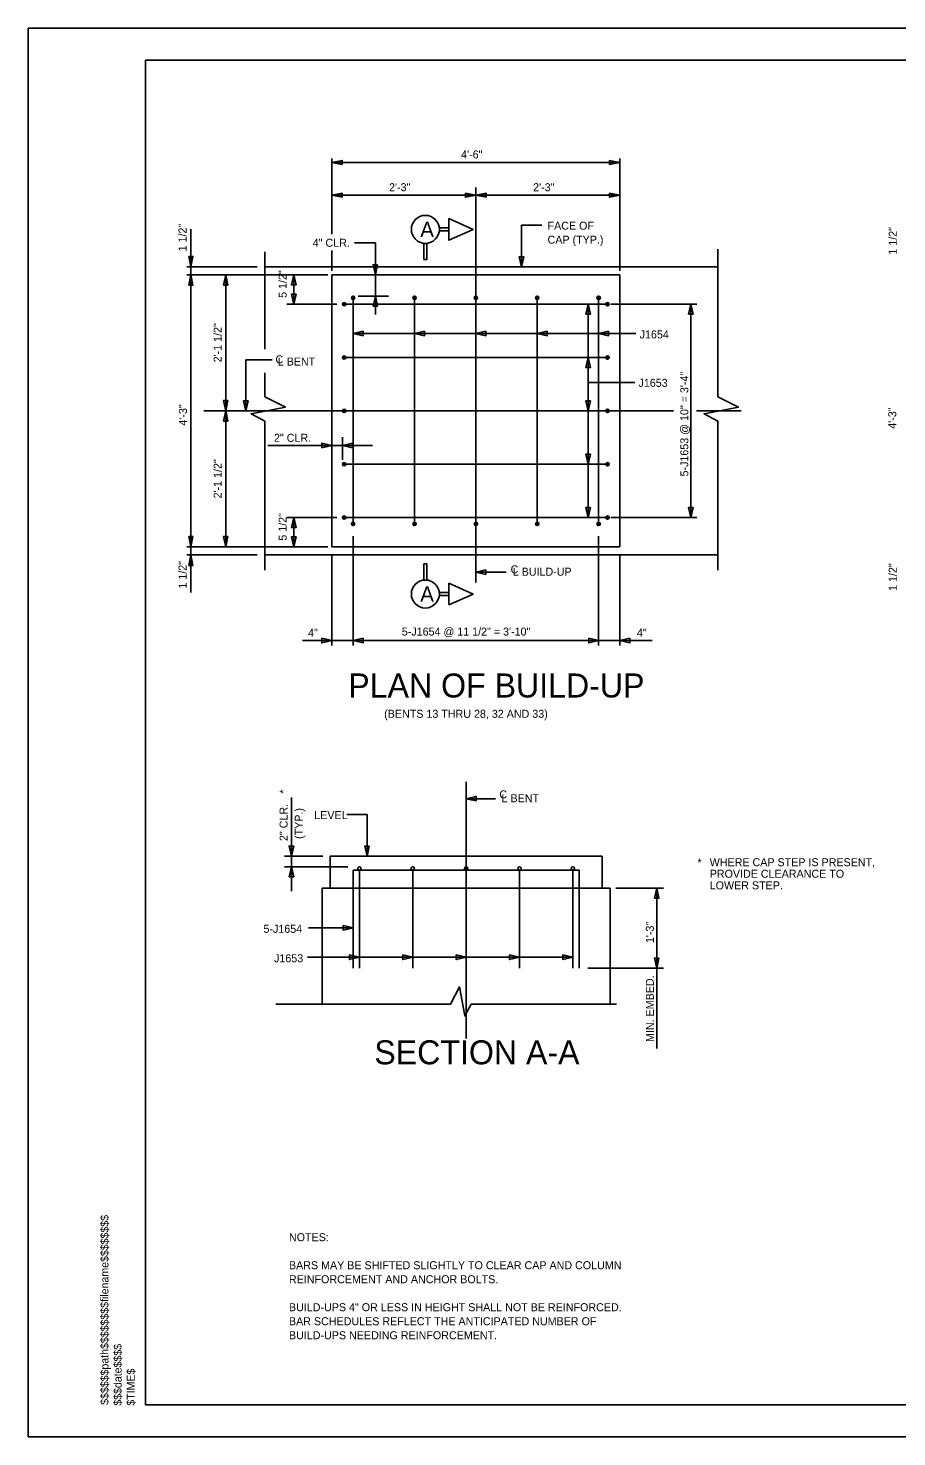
# Model space of a CAD drawing. Extents: x -133.1 to -97, y -58.4 to -36.4.
# Drawn here: x -133.14 to -119.58, y -58.4 to -36.4 of the extents above; entities that cross this region are included whole.
import ezdxf

# ---------------------------------------------------------------- set-up
doc = ezdxf.new("R2010")
doc.units = 0
for name, color, linetype in [('BR_AUTO DIMENSION', 7, 'Continuous'), ('BR_BORDER LINES', 7, 'Continuous'), ('BR_CENTER LINES', 7, 'Continuous'), ('BR_CONCRETE', 7, 'Continuous'), ('BR_REBAR', 7, 'Continuous'), ('BR_TEXT', 7, 'Continuous'), ('Default', 7, 'Continuous'), ('Level 31', 7, 'Continuous'), ('RD_SHT_ID', 7, 'Continuous')]:
    doc.layers.add(name, color=color, linetype=linetype)

msp = doc.modelspace()

# ---------------------------------------------------------------- linework, layer by layer
at = {"layer": 'BR_AUTO DIMENSION'}
for p, q in [((-128.4, -39.615), (-128.4, -38.433)), ((-128.4, -38.495), (-123.9, -38.495)), ((-123.9, -40.188), (-123.9, -38.433)), ((-126.15, -38.889), (-126.15, -39.254)), ((-128.4, -39.008), (-126.15, -39.008)), ((-123.9, -39.008), (-126.15, -39.008)), ((-130.599, -40.25), (-130.599, -39.536)), ((-125.436, -39.475), (-125.436, -40.125)), ((-125.436, -39.475), (-125.119, -39.475)), ((-127.72, -39.75), (-128.044, -39.75)), ((-127.72, -40.871), (-127.72, -39.75)), ((-128.4, -40.188), (-128.4, -39.869)), ((-129.565, -40.125), (-130.666, -40.125)), ((-128.463, -40.25), (-130.662, -40.25)), ((-130.599, -44.5), (-130.599, -40.25)), ((-130.057, -40.25), (-130.057, -42.375)), ((-128.995, -40.25), (-128.995, -40.709)), ((-127.988, -40.584), (-127.513, -40.584)), ((-128.321, -40.709), (-129.102, -40.709)), ((-124.396, -40.709), (-124.396, -44.042)), ((-124.045, -40.709), (-122.702, -40.709)), ((-122.795, -44.042), (-122.795, -40.709)), ((-128.067, -41.166), (-123.652, -41.166)), ((-129.743, -41.576), (-129.743, -42.375)), ((-129.331, -41.576), (-129.743, -41.576)), ((-124.396, -41.935), (-123.667, -41.935)), ((-130.114, -42.375), (-129.978, -42.375)), ((-130.057, -42.375), (-130.057, -44.5)), ((-128.233, -42.784), (-128.233, -43.139)), ((-127.765, -42.916), (-129.399, -42.916)), ((-128.321, -44.042), (-129.102, -44.042)), ((-128.995, -44.5), (-128.995, -44.042)), ((-124.045, -44.042), (-122.702, -44.042)), ((-128.067, -44.333), (-128.067, -46.038)), ((-124.233, -44.333), (-124.233, -46.038)), ((-129.565, -44.625), (-130.666, -44.625)), ((-128.463, -44.5), (-130.662, -44.5)), ((-130.599, -44.5), (-130.599, -45.214)), ((-128.4, -44.625), (-128.4, -46.038)), ((-123.9, -44.625), (-123.9, -46.038)), ((-126.15, -44.895), (-125.679, -44.895)), ((-128.856, -45.963), (-123.398, -45.963)), ((-129.03, -48.412), (-129.03, -49.877)), ((-126.302, -48.432), (-125.842, -48.432)), ((-128.167, -48.679), (-127.85, -48.679)), ((-127.85, -48.679), (-127.85, -49.329)), ((-128.541, -49.329), (-129.139, -49.329)), ((-128.152, -49.496), (-129.139, -49.496)), ((-123.964, -49.83), (-123.22, -49.83)), ((-123.327, -49.83), (-123.327, -52.333)), ((-128.067, -50.449), (-128.762, -50.449)), ((-124.635, -50.908), (-128.78, -50.908)), ((-128.385, -50.908), (-128.465, -50.908)), ((-127.135, -50.908), (-127.215, -50.908)), ((-126.302, -50.908), (-126.382, -50.908)), ((-125.968, -50.908), (-126.048, -50.908)), ((-125.468, -50.908), (-125.548, -50.908)), ((-124.635, -50.908), (-124.715, -50.908)), ((-124.401, -51.08), (-123.22, -51.08)), ((-123.964, -51.08), (-123.22, -51.08))]:
    msp.add_line(p, q, dxfattribs=at)
for points in [[(-128.238, -38.527), (-128.4, -38.495), (-128.238, -38.464)], [(-124.063, -38.464), (-123.9, -38.495), (-124.063, -38.527)], [(-128.238, -39.039), (-128.4, -39.008), (-128.238, -38.976)], [(-126.313, -38.976), (-126.15, -39.008), (-126.313, -39.039)], [(-125.988, -39.039), (-126.15, -39.008), (-125.988, -38.976)], [(-124.063, -38.976), (-123.9, -39.008), (-124.063, -39.039)], [(-130.631, -39.963), (-130.599, -40.125), (-130.568, -39.963)], [(-125.4, -39.969), (-125.436, -40.125), (-125.472, -39.969)], [(-130.631, -40.413), (-130.599, -40.25), (-130.568, -40.413)], [(-130.089, -40.413), (-130.057, -40.25), (-130.026, -40.413)], [(-128.959, -40.406), (-128.995, -40.25), (-129.031, -40.406)], [(-127.684, -40.094), (-127.72, -40.25), (-127.756, -40.094)], [(-129.031, -40.553), (-128.995, -40.709), (-128.959, -40.553)], [(-127.756, -40.74), (-127.72, -40.584), (-127.684, -40.74)], [(-124.432, -40.865), (-124.396, -40.709), (-124.36, -40.865)], [(-122.831, -40.865), (-122.795, -40.709), (-122.759, -40.865)], [(-127.911, -41.13), (-128.067, -41.166), (-127.911, -41.202)], [(-126.952, -41.13), (-127.108, -41.166), (-126.952, -41.202)], [(-125.994, -41.13), (-126.15, -41.166), (-125.994, -41.202)], [(-125.036, -41.13), (-125.192, -41.166), (-125.036, -41.202)], [(-124.077, -41.13), (-124.233, -41.166), (-124.077, -41.202)], [(-124.432, -41.698), (-124.396, -41.542), (-124.36, -41.698)], [(-130.026, -42.213), (-130.057, -42.375), (-130.089, -42.213)], [(-129.707, -42.219), (-129.743, -42.375), (-129.779, -42.219)], [(-124.36, -42.219), (-124.396, -42.375), (-124.432, -42.219)], [(-130.089, -42.538), (-130.057, -42.375), (-130.026, -42.538)], [(-128.556, -42.952), (-128.4, -42.916), (-128.556, -42.88)], [(-128.077, -42.88), (-128.233, -42.916), (-128.077, -42.952)], [(-124.36, -43.053), (-124.396, -43.209), (-124.432, -43.053)], [(-124.36, -43.886), (-124.396, -44.042), (-124.432, -43.886)], [(-122.759, -43.886), (-122.795, -44.042), (-122.831, -43.886)], [(-129.031, -44.198), (-128.995, -44.042), (-128.959, -44.198)], [(-130.568, -44.338), (-130.599, -44.5), (-130.631, -44.338)], [(-130.026, -44.338), (-130.057, -44.5), (-130.089, -44.338)], [(-128.959, -44.344), (-128.995, -44.5), (-129.031, -44.344)], [(-130.631, -44.788), (-130.599, -44.625), (-130.568, -44.788)], [(-125.994, -44.931), (-126.15, -44.895), (-125.994, -44.859)], [(-128.556, -45.927), (-128.4, -45.963), (-128.556, -45.999)], [(-127.911, -45.999), (-128.067, -45.963), (-127.911, -45.927)], [(-124.389, -45.927), (-124.233, -45.963), (-124.389, -45.999)], [(-123.744, -45.927), (-123.9, -45.963), (-123.744, -45.999)], [(-126.146, -48.468), (-126.302, -48.432), (-126.146, -48.396)], [(-128.994, -49.173), (-129.03, -49.329), (-129.066, -49.173)], [(-127.814, -49.173), (-127.85, -49.329), (-127.886, -49.173)], [(-129.066, -49.652), (-129.03, -49.496), (-128.994, -49.652)], [(-123.363, -49.986), (-123.327, -49.83), (-123.291, -49.986)], [(-128.223, -50.413), (-128.067, -50.449), (-128.223, -50.485)], [(-128.124, -50.872), (-127.968, -50.908), (-128.124, -50.944)], [(-127.291, -50.872), (-127.135, -50.908), (-127.291, -50.944)], [(-126.458, -50.872), (-126.302, -50.908), (-126.458, -50.944)], [(-125.624, -50.872), (-125.468, -50.908), (-125.624, -50.944)], [(-124.791, -50.872), (-124.635, -50.908), (-124.791, -50.944)], [(-123.291, -50.924), (-123.327, -51.08), (-123.363, -50.924)]]:
    msp.add_lwpolyline(points, close=True, dxfattribs=at)
at = {"layer": 'BR_BORDER LINES'}
for p, q in [((-97.642, -36.899), (-131.308, -36.899)), ((-131.308, -57.899), (-131.308, -36.899)), ((-131.308, -57.899), (-97.642, -57.899))]:
    msp.add_line(p, q, dxfattribs=at)
at = {"layer": 'BR_CENTER LINES'}
for p, q in [((-126.15, -39.008), (-126.15, -45.056)), ((-130.399, -42.375), (-123.065, -42.375)), ((-122.703, -42.375), (-122.007, -42.375)), ((-126.302, -48.171), (-126.302, -52.18))]:
    msp.add_line(p, q, dxfattribs=at)
at = {"layer": 'BR_CONCRETE'}
for p, q in [((-129.444, -40.125), (-122.37, -40.125)), ((-128.4, -40.25), (-123.9, -40.25)), ((-128.4, -40.25), (-128.4, -44.5)), ((-123.9, -40.25), (-123.9, -44.5)), ((-129.444, -44.625), (-122.37, -44.625)), ((-128.4, -44.5), (-123.9, -44.5)), ((-128.427, -49.329), (-128.427, -49.83)), ((-128.427, -49.329), (-124.177, -49.329)), ((-124.177, -49.329), (-124.177, -49.83)), ((-128.552, -49.83), (-128.552, -51.642)), ((-128.552, -49.83), (-124.052, -49.83)), ((-124.052, -49.83), (-124.052, -51.642))]:
    msp.add_line(p, q, dxfattribs=at)
at = {"layer": 'BR_REBAR'}
for p, q in [((-128.067, -44.167), (-128.067, -40.584)), ((-127.108, -44.167), (-127.108, -40.584)), ((-126.15, -44.167), (-126.15, -40.584)), ((-125.192, -44.167), (-125.192, -40.584)), ((-124.233, -44.167), (-124.233, -40.584)), ((-128.233, -40.709), (-124.067, -40.709)), ((-128.233, -41.542), (-124.067, -41.542)), ((-128.233, -42.375), (-124.067, -42.375)), ((-128.233, -43.209), (-124.067, -43.209)), ((-128.233, -44.042), (-124.067, -44.042)), ((-128.067, -49.548), (-128.067, -51.08)), ((-124.536, -49.548), (-128.067, -49.548)), ((-127.968, -51.08), (-127.968, -49.548)), ((-127.135, -51.08), (-127.135, -49.548)), ((-126.302, -51.08), (-126.302, -49.548)), ((-125.468, -51.08), (-125.468, -49.548)), ((-124.635, -51.08), (-124.635, -49.548)), ((-124.536, -49.548), (-124.536, -51.08))]:
    msp.add_line(p, q, dxfattribs=at)
for centre, radius in [((-128.207, -40.709), 0.026), ((-128.067, -40.61), 0.0261), ((-127.108, -40.61), 0.0261), ((-126.15, -40.61), 0.0261), ((-125.192, -40.61), 0.0261), ((-124.233, -40.61), 0.0261), ((-124.093, -40.709), 0.026), ((-128.207, -41.542), 0.026), ((-124.093, -41.542), 0.026), ((-128.207, -42.375), 0.026), ((-124.093, -42.375), 0.026), ((-128.207, -43.209), 0.026), ((-124.093, -43.209), 0.026), ((-128.207, -44.042), 0.026), ((-128.067, -44.141), 0.0261), ((-127.108, -44.141), 0.0261), ((-126.15, -44.141), 0.0261), ((-125.192, -44.141), 0.0261), ((-124.233, -44.141), 0.0261), ((-124.093, -44.042), 0.026), ((-127.968, -49.522), 0.0261), ((-127.135, -49.522), 0.0261), ((-126.302, -49.522), 0.0261), ((-125.468, -49.522), 0.0261), ((-124.635, -49.522), 0.0261)]:
    msp.add_circle(centre, radius, dxfattribs=at)
at = {"layer": 'BR_TEXT'}
for points in [[(-126.57, -39.373), (-126.195, -39.541), (-126.57, -39.71)], [(-126.72, -39.566), (-126.57, -39.566), (-126.57, -39.516), (-126.72, -39.516)], [(-126.964, -40.011), (-126.914, -40.011), (-126.914, -39.76), (-126.964, -39.76)], [(-126.964, -44.767), (-126.914, -44.767), (-126.914, -45.017), (-126.964, -45.017)], [(-126.57, -45.405), (-126.195, -45.236), (-126.57, -45.067)], [(-126.72, -45.211), (-126.57, -45.211), (-126.57, -45.261), (-126.72, -45.261)]]:
    msp.add_lwpolyline(points, close=True, dxfattribs=at)
for centre in [(-126.939, -39.541), (-126.939, -45.236)]:
    msp.add_circle(centre, 0.219, dxfattribs=at)
at = {"layer": 'Default'}
for p, q in [((-129.444, -39.89), (-129.444, -41.41)), ((-122.37, -39.851), (-122.37, -42.154)), ((-129.444, -41.782), (-129.444, -42.154)), ((-129.444, -42.537), (-129.444, -44.865)), ((-122.37, -42.537), (-122.37, -44.865)), ((-129.272, -51.642), (-126.547, -51.642)), ((-126.224, -51.642), (-123.957, -51.642))]:
    msp.add_line(p, q, dxfattribs=at)
for points in [[(-129.444, -42.537), (-129.661, -42.42), (-129.125, -42.319), (-129.444, -42.154)], [(-122.37, -42.537), (-122.587, -42.42), (-122.051, -42.319), (-122.37, -42.154)], [(-126.224, -51.642), (-126.323, -51.825), (-126.408, -51.373), (-126.547, -51.642)]]:
    msp.add_lwpolyline(points, dxfattribs=at)
at = {"layer": 'Level 31'}
msp.add_lwpolyline([(-133.141, -58.399), (-97.141, -58.399), (-97.141, -36.399), (-133.141, -36.399)], close=True, dxfattribs=at)

# ---------------------------------------------------------------- texts
at = {"layer": 'BR_AUTO DIMENSION'}
for s, p in [('4\'-6"', (-126.381, -38.433)), ('2\'-3"', (-127.506, -38.945)), ('2\'-3"', (-125.256, -38.945)), ('FACE OF', (-125.031, -39.546)), ('4" CLR.', (-128.698, -39.813)), ('CAP (TYP.)', (-125.031, -39.765)), ('J1654', (-123.593, -41.244)), ('J1653', (-123.611, -42)), ('2" CLR.', (-129.303, -42.859)), ('C', (-125.608, -44.913)), ('L BUILD-UP', (-125.574, -44.95)), ('5-J1654 @ 11 1/2" = 3\'-10"', (-127.307, -45.885)), ('(BENTS 13 THRU 28, 32 AND 33)', (-127.582, -47.169)), ('NOTES:', (-129.069, -55.344)), ('BARS MAY BE SHIFTED SLIGHTLY TO CLEAR CAP AND COLUMN', (-129.069, -55.781)), ('REINFORCEMENT AND ANCHOR BOLTS.', (-129.069, -56)), ('BUILD-UPS 4" OR LESS IN HEIGHT SHALL NOT BE REINFORCED.', (-129.069, -56.437)), ('BAR SCHEDULES REFLECT THE ANTICIPATED NUMBER OF', (-129.069, -56.656)), ('BUILD-UPS NEEDING REINFORCEMENT.', (-129.069, -56.875))]:
    msp.add_text(s, height=0.125, dxfattribs=at).set_placement(p)
for s, rotation, p in [('2\'-1 1/2"', 90, (-130.12, -41.618)), ('5-J1653 @ 10" = 3\'-4"', 90, (-122.833, -43.4)), ('4\'-3"', 90, (-130.662, -42.606)), ('4\'-3"', 90, (-119.586, -42.655)), ('2\'-1 1/2"', 90, (-130.12, -43.743)), ('4"', 360, (-128.77, -45.904)), ('4"', 360, (-123.636, -45.904)), ('*', 90, (-129.091, -48.355)), ('C', 360, (-125.783, -48.427)), ('L BENT', 360, (-125.749, -48.488)), ('2" CLR.', 90, (-129.09, -49.094)), ('(TYP.)', 90, (-128.853, -49.061)), ('LEVEL', 360, (-128.674, -48.752)), ('*', 360, (-122.689, -49.491)), ('WHERE CAP STEP IS PRESENT,', 360, (-122.499, -49.487)), ('PROVIDE CLEARANCE TO', 360, (-122.499, -49.667)), ('LOWER STEP.', 360, (-122.499, -49.848)), ('1\'-3" ', 90, (-123.371, -50.688)), ('5-J1654', 360, (-129.467, -50.527)), ('J1653', 360, (-129.302, -50.987)), ('MIN. EMBED.', 90, (-123.371, -52.232))]:
    msp.add_text(s, height=0.125, rotation=rotation, dxfattribs=at).set_placement(p)
at = {"layer": 'BR_TEXT'}
for s, height, rotation, p in [('1 1/2"', 0.125, 90, (-130.668, -39.885)), ('1 1/2"', 0.125, 90, (-119.579, -39.935)), ('5 1/2"', 0.125, 90, (-129.105, -40.611)), ('C', 0.125, 360, (-129.279, -41.633)), ('L BENT', 0.125, 360, (-129.244, -41.668)), ('5 1/2"', 0.125, 90, (-129.105, -44.403)), ('1 1/2"', 0.125, 90, (-130.668, -45.151)), ('1 1/2"', 0.125, 90, (-119.579, -45.187)), ('SECTION A-A', 0.375, 360, (-127.736, -52.581))]:
    msp.add_text(s, height=height, rotation=rotation, dxfattribs=at).set_placement(p)
for s, height, p in [('A', 0.24, (-127.019, -39.661)), ('A', 0.24, (-127.019, -45.356)), ('PLAN OF BUILD-UP', 0.375, (-128.143, -46.852))]:
    msp.add_text(s, height=height, dxfattribs=at).set_placement(p)
at = {"layer": 'RD_SHT_ID'}
for s, height, p in [('$$$$$$path$$$$$$$$filename$$$$$$$$', 0.12347, (-131.887, -57.899)), ('$$$date$$$$', 0.12347, (-131.682, -57.912)), ('$TIME$', 0.1235, (-131.477, -57.912))]:
    msp.add_text(s, height=height, rotation=90, dxfattribs=at).set_placement(p)

doc.saveas('drawing.dxf')
